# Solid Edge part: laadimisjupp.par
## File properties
Title: laadimisjupp
Author: Stella-Marii
Template: Iso Metric Part.par
Last saved by: Stella-Marii
Revision: 23
Application: Solid Edge
Document Number: 19
Density: 1024,000 kg/m^3
Accuracy: 0,990
Username: Stella-Marii
Material: ABS Plastic, high impact
Face Style: Red
Fill Style: ANSI34(Plastic)
Virtual Style: Red (Shiny)
Grouping: Non-metals\Plastics
LibraryName: Materials
Coef. of Thermal Exp: 9e-05
Thermal Conductivity: 0.2
Specific Heat: 0.0
Modulus of Elasticity: 1378951400.0
Poisson's Ratio: 0.4
Yield Stress: 31026406.5
Ultimate Stress: 0.0
Elongation: 0.0
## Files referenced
..\scooter.asm
@C:\Users\Stella-Marii\DATA\KOOL\Solid Edge - scooter\scooter.asm
C:\Users\Stella-Marii\DATA\KOOL\Solid Edge - scooter\raami alumine toru.par
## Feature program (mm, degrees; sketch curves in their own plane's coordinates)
sketch for "unnamed Protrusion 1" plane through (0, 0, 0) normal (1, 0, 0) x-axis (0, 1, 0)
  circle centre (0, 0) radius 24
extrude "unnamed Protrusion 1" add finite 100 along -normal
sketch for "ExtrudedCutout_4" plane through (0, 0, 0) normal (0, -1, 0) x-axis (1, 0, 0)
extrude "ExtrudedCutout_4" cut finite 193.8957 symmetric
sketch for "ExtrudedCutout_5" plane through (0, 0, -50) normal (0, 0, 1) x-axis (1, 0, 0)
  circle centre (-33.4918, 0) radius 10.163
extrude "ExtrudedCutout_5" cut finite 32 along +normal
sketch for "ExtrudedCutout_6" plane through (-40.7171, 0, -18) normal (0, 0, -1) x-axis (0, -1, 0)
extrude "ExtrudedCutout_6" cut finite 4 along -normal
fillet "Round_1" radius 0.7
sketch for "unnamed Cutout 1" plane through (0, 0, 0) normal (0, -1, 0) x-axis (1, 0, 0)
extrude "unnamed Cutout 1" cut finite 88.4855 symmetric
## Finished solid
Body 1: solid body, 12 faces, 14 edges, 4 vertices.
  Faces by surface: plane 5, cylinder 3, torus 3, blend 1
  Edges by curve: circle 8, line 4, intersection 2
Bounding box of the edges (mm; curved faces can reach further): 75.405 x 42.505 x 12.850, from (-75.4054, -21.2524, -24) to (0, 21.2524, -11.1505).
Cylindrical faces by radius (mm): R7.1836 x1, R10.163 x1, R24 x1
Toroidal faces (ring radius, tube radius in mm): R6.4836 r0.7 x1, R7.8836 r0.7 x1, R9.463 r0.7 x1
Planar faces by outward normal: +x 1, +z 1, -x 1, -z 2
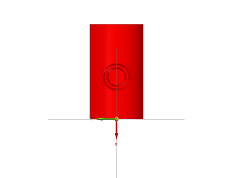
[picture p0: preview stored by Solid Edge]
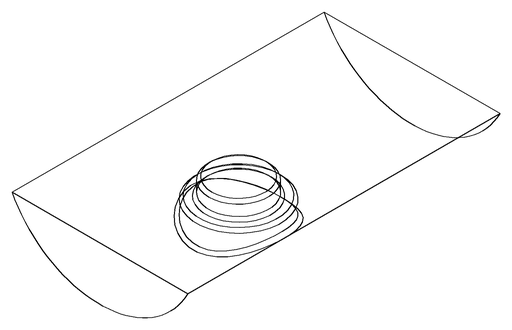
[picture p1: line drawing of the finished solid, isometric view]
